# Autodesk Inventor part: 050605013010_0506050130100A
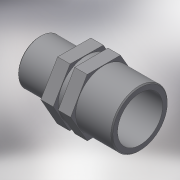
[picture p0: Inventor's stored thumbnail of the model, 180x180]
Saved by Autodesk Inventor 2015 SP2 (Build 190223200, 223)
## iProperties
Created: 2017-05
Part Number: 050605013010_0506050130100A
Material: Generic
Description: PLASSON REDUCING NIPPLE 1.1/4"-1"
Document SubType Name: Modeling
Designer: KIM
Density: 1 g/cm^3
Appearance: Default
Author: KIM
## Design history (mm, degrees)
derived "050605.ipt"
feature "Solid1::050605.ipt"
tag "TaggingFeature1"
body "Solid1"
other parameters: "d0" = 56, "d1" = 41.91, "d5" = 21, "d6" = 5.6, "d8" = 0.56, "d12" = 0, "d14" = 33.249, "d15" = 26.5992, "d16" = 33.528, "d17" = 19, "d18" = 2.8, "d19" = 46, "d21" = 0, "H_" = 56, "R_" = 41.91, "E_" = 46, "l_" = 21, "R_1" = 33.249, "l_1" = 19
